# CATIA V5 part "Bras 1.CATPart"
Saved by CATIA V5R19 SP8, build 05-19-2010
Part number: Bras 1
Publications: "Diamètre bielle", "Rayon bielle"
Bounding box of the stored display mesh (mm): x -1210.707 to 225, y -761.484 to 761.484, z -3411.667 to 75
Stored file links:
  C:\Users\ThinkMotion\Desktop\EU_thinkMotion\iao\IAO_MMS_Groupe3\fovide\fovide\Bras 1.CATPart
  C:\Users\ThinkMotion\Desktop\EU_thinkMotion\iao\IAO_MMS_Groupe3\fovide\fovide\fovide.CATProduct
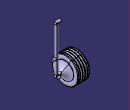
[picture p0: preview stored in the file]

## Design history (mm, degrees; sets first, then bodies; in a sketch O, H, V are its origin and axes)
Parameters
  `Diamètre bielle` = 150 mm
  `Rayon bielle` = 75 mm {= `Diamètre bielle` /2}
  rainure = 40 mm
  espace = 100 mm
  profondeur = 40 mm
Set1
  Point1 "Point.D": linked copy from another document
  Point2 "Point.F": linked copy from another document
  Point3 "Point.C": linked copy from another document
Body1 (main body)
  Sketch1 on yz-plane, origin (0, 0, 0), H (0, 1, 0), V (0, 0, 1)
    point P1 (0, 0)
    line L1 (0, 0) -> (75, 0)
    line L2 (75, 0) -> (75, -2650)
    line L3 (75, -2650) -> (0, -2650)
    line L4 (0, -2650) -> (0, 0)
    point P4 (0, -2650)
    reference projected point E1 (0, 0) from Point1
    reference projected point E2 (0, -2650) from Point2
    length L1 = 75 {= `Diamètre bielle` /2}
    horizontal: L1 H, L3 H
    vertical: L2 V, L4 V
    coincidence: P1 E1, P4 E2
  Shaft1: profile Sketch1, axis Sketch1.L4, angle 360
  Sketch2 on yz-plane, origin (0, 0, 0), H (0, 1, 0), V (0, 0, 1)
    circle A1 centre (0, 0) radius 75
    point P1 (0, 0)
    reference projected point E1 (0, 0) from Point1
    radius A1 = 75 {= `Diamètre bielle` /2}
    coincidence: P1 E1
  Pad1: profile Sketch2, direction (1, 0, 0), length 75 {= `Diamètre bielle` /2}, opposite side length 225 {= `Diamètre bielle` *1.5}
  Sketch3 on yz-plane, origin (0, 0, 0), H (0, 1, 0), V (0, 0, 1)
    circle A1 centre (0, -1800) radius 75
    point P1 (0, -1800)
    reference projected point E1 (0, -1800) from Point3
    radius A1 = 75 {= `Diamètre bielle` /2}
    coincidence: P1 E1
  Pad2: profile Sketch3, direction (1, 0, 0), length 225 {= `Diamètre bielle` *1.5}
  Sketch4 on yz-plane, origin (0, 0, 0), H (0, 1, 0), V (0, 0, 1)
    circle A1 centre (0, -2650) radius 75
    point P1 (0, -2650)
    reference projected point E1 (0, -2650) from Point2
    radius A1 = 75 {= `Diamètre bielle` /2}
    coincidence: P1 E1
  Pad3: profile Sketch4, direction (1, 0, 0), length 75 {= `Diamètre bielle` /2}, opposite side length 225 {= `Diamètre bielle` *1.5}
  Sketch5 on zx-plane, origin (0, 0, 0), H (-1, 0, 0), V (0, 0, 1)
    point P1 (225, -2575)
    point P2 (500, -2147.2732)
    line L1 (425, -2650) -> (225, -2650)
    point P4 (225, -2650)
    line L2 (225, -2650) -> (225, -2575)
    reference projected point E1 (0, -2650) from Point2
    line L3 (500, -2147.2732) -> (480, -2147.2732)
    point P5 (480, -2147.2732)
    spline S1 through (225, -2575) (410, -2370) (480, -2147.2732)
    spline S2 through (500, -2147.2732) (480, -2030) (500, -1910)
    spline S3 through (500, -1910) (520, -1890) (530, -1888.3331)
    spline S4 through (1160.3839, -1888.3331) (1171.1626, -1889.6285) (1190.3839, -1907.2732)
    spline S5 through (1190.3839, -1907.2732) (1210.3839, -2027.2732) (1191.2384, -2147.2732)
    point P6 (1190.3839, -2650)
    line L4 (1190.3839, -2650) -> (425, -2650)
    line L5 (530, -1888.3331) -> (550, -1888.3331)
    point P7 (530, -1888.3331)
    point P8 (550, -1888.3331)
    line L6 (1160.3839, -1888.3331) -> (1140.3839, -1888.3331)
    point P9 (1160.3839, -1888.3331)
    line L7 (615, -1888.3331) -> (615, -1928.3331)
    line L8 (615, -1928.3331) -> (655, -1928.3331)
    line L9 (655, -1928.3331) -> (655, -1888.3331)
    line L10 (615, -1888.3331) -> (550, -1888.3331)
    line L11 (755, -1888.3331) -> (755, -1928.3331)
    point P15 (755, -1888.3331)
    point P16 (755, -1928.3331)
    line L12 (755, -1928.3331) -> (795, -1928.3331)
    line L13 (795, -1928.3331) -> (795, -1888.3331)
    point P18 (795, -1888.3331)
    line L14 (655, -1888.3331) -> (755, -1888.3331)
    line L15 (895, -1888.3331) -> (895, -1928.3331)
    point P20 (895, -1928.3331)
    line L16 (895, -1928.3331) -> (935, -1928.3331)
    line L17 (935, -1928.3331) -> (935, -1888.3331)
    point P22 (935, -1888.3331)
    line L18 (935, -1888.3331) -> (1035, -1888.3331)
    line L19 (1035, -1888.3331) -> (1035, -1928.3331)
    point P24 (1035, -1928.3331)
    line L20 (1035, -1928.3331) -> (1075, -1928.3331)
    line L21 (1075, -1928.3331) -> (1075, -1888.3331)
    point P26 (1075, -1888.3331)
    line L22 (1075, -1888.3331) -> (1140.3839, -1888.3331)
    line L23 (895, -1888.3331) -> (795, -1888.3331)
    line L24 (1191.2384, -2147.2732) -> (1191.2384, -2492.2344)
    point P27 (1191.2384, -2147.2732)
    point P28 (1191.2384, -2492.2344)
    spline S6 through (1191.2384, -2492.2344) (1200.3879, -2497.5959) (1210.707, -2512.865)
    line L25 (1210.707, -2512.865) -> (1210.707, -2650)
    point P29 (1210.707, -2512.865)
    point P30 (1210.707, -2650)
    line L26 (1210.707, -2650) -> (1190.3839, -2650)
    point P31 (225, -2575)
    point P32 (480, -2147.2732)
    point P33 (500, -2147.2732)
    point P34 (500, -1910)
    point P35 (500, -1910)
    point P36 (530, -1888.3331)
    point P37 (1160.3839, -1888.3331)
    point P38 (1190.3839, -1907.2732)
    point P39 (1190.3839, -1907.2732)
    point P40 (1191.2384, -2147.2732)
    point P41 (1191.2384, -2492.2344)
    point P42 (1210.707, -2512.865)
    length L1 = 200
    distance P4 E1 = 225 {= `Diamètre bielle` *1.5}
    length L18 = 100 {= espace}
    length L23 = 100 {= espace}
    length L14 = 100 {= espace}
    length L20 = 40 {= rainure}
    length L16 = 40 {= rainure}
    length L12 = 40 {= rainure}
    length L8 = 40 {= rainure}
    length L10 = 65
    length L9 = 40 {= profondeur}
    length L2 = 75 {= `Rayon bielle`}
    horizontal: L1 H, L3 H, L4 H, L5 H, L6 H, L8 H, L10 H, L12 H, L14 H, L16 H, L18 H, L20 H, L22 H, L23 H, L26 H
    vertical: L2 V, L7 V, L9 V, L11 V, L13 V, L15 V, L17 V, L19 V, L21 V, L24 V, L25 V
    coincidence: P31 P1, P32 P5, P33 P2, P35 P34, P38 P39, P40 L3, P6 L1, P36 P7, P37 P9, P15 L5, P16 L8, P18 L5, P20 L12, P22 L6, P24 L12, P26 L6, P40 P27, P41 P28, P42 P29, P30 L4
    fix: P8, P9, P30
  Shaft2: profile Sketch5, axis Sketch5.L1, angle 360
